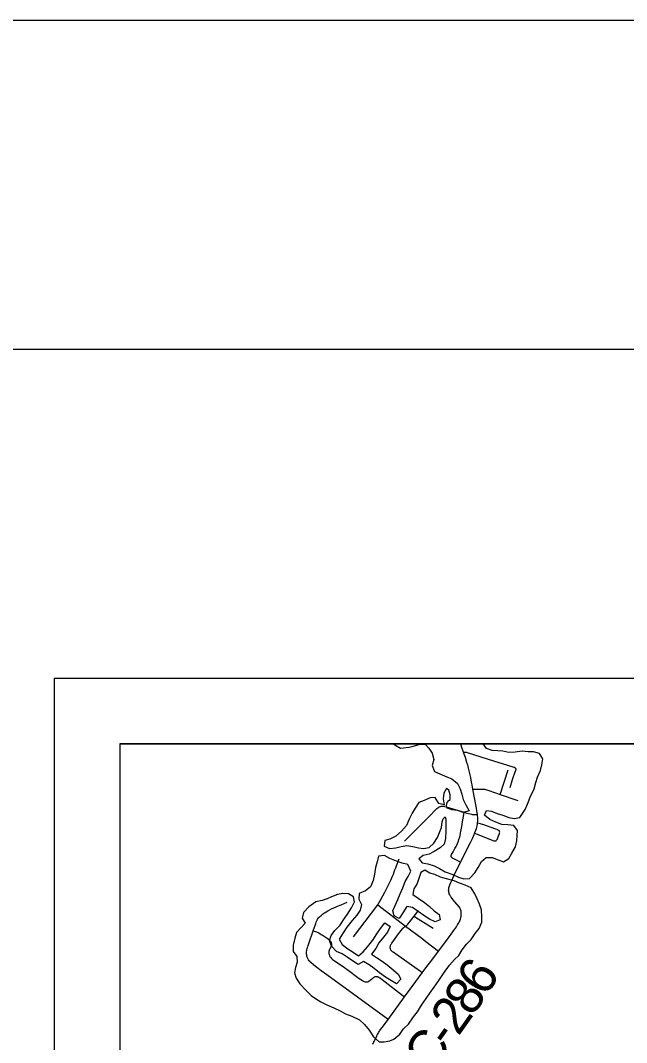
# Model space of a CAD drawing. Extents: x 0 to 34, y -5.4 to 22.
# Drawn here: x 1.949 to 2.87, y 20.446 to 22 of the extents above; entities that cross this region are included whole.
import ezdxf

# ---------------------------------------------------------------- set-up
doc = ezdxf.new("R2010")
doc.units = 0
for name, color, linetype in [('GM_X_County_Road', 7, 'Continuous'), ('GM_X_County_Road_Text', 7, 'Continuous'), ('GM_X_Major_Lake', 7, 'Continuous'), ('GM_X_Rail_Line', 7, 'Continuous'), ('GM_X_Township_Road', 7, 'Continuous'), ('SH_Border', 7, 'Continuous'), ('SH_Cut_Line', 7, 'Continuous'), ('SH_Data', 7, 'Continuous')]:
    doc.layers.add(name, color=color, linetype=linetype)

msp = doc.modelspace()

# ---------------------------------------------------------------- linework, layer by layer
at = {"layer": 'GM_X_County_Road'}
for points in [[(2.5077, 20.4812), (2.533, 20.5158), (2.5499, 20.5391), (2.5596, 20.552), (2.5668, 20.5615), (2.5726, 20.5692), (2.5843, 20.5849), (2.5956, 20.5999), (2.6036, 20.6107), (2.6089, 20.618), (2.6118, 20.6221), (2.6136, 20.625), (2.6151, 20.6276), (2.6162, 20.6295), (2.617, 20.6313), (2.6177, 20.6335), (2.6182, 20.6357), (2.6187, 20.6381), (2.619, 20.6408), (2.6191, 20.6431), (2.619, 20.6448), (2.6188, 20.6457), (2.6185, 20.6472), (2.6181, 20.6484), (2.6172, 20.6504), (2.6157, 20.6526), (2.6092, 20.6602), (2.6066, 20.6633), (2.6052, 20.665), (2.604, 20.6666), (2.6033, 20.6676), (2.6021, 20.6695), (2.6016, 20.6705), (2.6009, 20.672), (2.6006, 20.673), (2.6002, 20.6747), (2.6, 20.6765), (2.5999, 20.6779), (2.6, 20.6795), (2.6002, 20.6812), (2.6006, 20.6831), (2.601, 20.6842), (2.6016, 20.6859), (2.6031, 20.6896), (2.6045, 20.6926), (2.6079, 20.6997), (2.6179, 20.7206), (2.6333, 20.7502), (2.6361, 20.7565), (2.6386, 20.7625), (2.6394, 20.7645), (2.6398, 20.7654), (2.6412, 20.7692), (2.6421, 20.7716), (2.6426, 20.7735), (2.6431, 20.7756), (2.6436, 20.7779), (2.6439, 20.7797), (2.644, 20.7804), (2.6441, 20.7826), (2.6442, 20.7852), (2.6441, 20.7883), (2.6438, 20.7914), (2.6436, 20.7926), (2.6433, 20.7955), (2.6428, 20.7986), (2.6421, 20.8025), (2.6398, 20.8154), (2.6367, 20.8315), (2.6355, 20.8379), (2.6348, 20.842), (2.6342, 20.8453), (2.6335, 20.849), (2.6326, 20.8532), (2.6312, 20.8592), (2.6302, 20.8632), (2.6295, 20.8657), (2.6289, 20.8678), (2.6277, 20.8718), (2.6254, 20.8793), (2.6236, 20.8846), (2.6226, 20.8874), (2.622, 20.8893), (2.6206, 20.8934), (2.6184, 20.8999), (2.6184, 20.9)], [(2.4848, 20.4436), (2.4907, 20.4562), (2.4916, 20.4582), (2.4926, 20.4598), (2.4934, 20.4613), (2.4938, 20.4618), (2.4947, 20.4633), (2.4954, 20.4645), (2.4963, 20.4658), (2.4991, 20.4696), (2.5077, 20.4812)]]:
    msp.add_lwpolyline(points, dxfattribs=at)
at = {"layer": 'GM_X_Major_Lake'}
for points in [[(2.5163, 20.9), (2.518, 20.8988), (2.5267, 20.8938), (2.54, 20.8951), (2.5457, 20.8969), (2.5552, 20.899), (2.5643, 20.8996), (2.5699, 20.8938), (2.575, 20.8861), (2.5775, 20.8762), (2.5747, 20.8672), (2.5783, 20.8584), (2.5866, 20.8544), (2.5969, 20.8503)], [(2.5947, 20.7058), (2.6061, 20.7018), (2.6148, 20.6975), (2.6231, 20.6951), (2.6314, 20.6957), (2.6399, 20.7039), (2.6446, 20.7122), (2.65, 20.7216), (2.6569, 20.7276), (2.666, 20.7274), (2.6754, 20.7239), (2.6834, 20.7211), (2.6914, 20.7259), (2.6961, 20.7342), (2.7015, 20.7439), (2.7035, 20.7526), (2.704, 20.761), (2.7045, 20.7686), (2.699, 20.7759), (2.6899, 20.7771), (2.6808, 20.7777), (2.6714, 20.7812), (2.6627, 20.7852), (2.6545, 20.7917), (2.6573, 20.7989), (2.6652, 20.798), (2.6735, 20.7945), (2.6825, 20.7917), (2.6916, 20.7885), (2.6995, 20.7869), (2.7083, 20.7882), (2.7164, 20.8006), (2.7196, 20.8086), (2.7239, 20.8191), (2.7298, 20.8316), (2.7326, 20.8414), (2.735, 20.8497), (2.7393, 20.8599), (2.7417, 20.8682), (2.743, 20.8773), (2.7382, 20.8857), (2.7287, 20.8881), (2.7208, 20.8883), (2.7117, 20.8892), (2.701, 20.8874), (2.6916, 20.8872), (2.6825, 20.8889), (2.6746, 20.8894), (2.6662, 20.8902), (2.6572, 20.893), (2.6525, 20.9)], [(2.5969, 20.8503), (2.6046, 20.8468), (2.6135, 20.8398), (2.6176, 20.8318), (2.6197, 20.8238), (2.6219, 20.8154), (2.6263, 20.8066), (2.6311, 20.7986), (2.622, 20.7957), (2.6133, 20.7988), (2.6054, 20.8001), (2.5978, 20.8023), (2.5966, 20.8065), (2.5977, 20.8113), (2.6004, 20.8142), (2.6024, 20.8156), (2.6024, 20.8228), (2.6001, 20.8296), (2.5966, 20.8323)], [(2.5966, 20.8323), (2.5925, 20.8255), (2.5916, 20.8168), (2.593, 20.8077), (2.5851, 20.8097), (2.5792, 20.8185), (2.5716, 20.8183), (2.5628, 20.8139), (2.5548, 20.811), (2.5489, 20.8024), (2.5443, 20.7949), (2.5399, 20.7859), (2.5356, 20.7761), (2.5283, 20.7675), (2.5194, 20.7597), (2.5106, 20.7553), (2.503, 20.7531), (2.5017, 20.7448), (2.51, 20.7413), (2.5195, 20.7419), (2.5279, 20.744), (2.5362, 20.7457), (2.5453, 20.7441), (2.554, 20.742), (2.5615, 20.7411), (2.5703, 20.7429), (2.5776, 20.7492), (2.583, 20.7578), (2.5862, 20.7653), (2.589, 20.7729), (2.5899, 20.7816), (2.5915, 20.7861), (2.5946, 20.7895)], [(2.5946, 20.7895), (2.5958, 20.7858), (2.5958, 20.7801), (2.5957, 20.7686), (2.5951, 20.7561), (2.5932, 20.7477), (2.5869, 20.7422), (2.5777, 20.7367), (2.5701, 20.7326), (2.5613, 20.7305), (2.5544, 20.7253), (2.5596, 20.7192), (2.5683, 20.7179), (2.5777, 20.7147), (2.5861, 20.7107), (2.5947, 20.7058)], [(2.5945, 20.6955), (2.5873, 20.6978), (2.579, 20.7014), (2.5711, 20.7038), (2.5636, 20.7081), (2.5575, 20.7044), (2.5519, 20.6878), (2.5472, 20.6796), (2.5455, 20.6713), (2.5534, 20.6654), (2.5631, 20.6592), (2.5706, 20.653), (2.5781, 20.6464), (2.5855, 20.641), (2.5869, 20.6326), (2.5793, 20.6297), (2.5706, 20.6337), (2.5624, 20.6391), (2.5534, 20.6453), (2.5448, 20.6512), (2.5361, 20.6532), (2.5303, 20.6435), (2.5248, 20.6345), (2.5169, 20.6388), (2.5148, 20.6464), (2.5187, 20.6547), (2.5227, 20.6637), (2.5262, 20.6724), (2.5302, 20.6814), (2.5337, 20.6908), (2.5384, 20.6987), (2.5424, 20.7066), (2.5376, 20.7169), (2.5293, 20.7186), (2.5206, 20.7217), (2.5105, 20.7261), (2.5022, 20.7304), (2.4931, 20.7294), (2.4911, 20.7211), (2.4887, 20.7121), (2.4873, 20.7019), (2.4853, 20.6924), (2.481, 20.683), (2.4736, 20.6767), (2.4641, 20.6727), (2.4632, 20.664), (2.4676, 20.6559)], [(2.5923, 20.551), (2.6014, 20.5637), (2.6087, 20.5723), (2.6156, 20.5787), (2.6203, 20.5873), (2.6269, 20.5959), (2.6342, 20.6027), (2.6404, 20.6117), (2.6462, 20.6196), (2.6505, 20.629), (2.6506, 20.6373), (2.6496, 20.648), (2.6468, 20.6567), (2.6435, 20.6644), (2.6398, 20.6724), (2.6339, 20.6812), (2.6248, 20.6856), (2.6162, 20.6883), (2.6083, 20.6919), (2.5945, 20.6955)], [(2.4676, 20.6559), (2.4652, 20.6476), (2.4601, 20.6398), (2.4532, 20.6316), (2.445, 20.6215), (2.4396, 20.6128), (2.4334, 20.6031), (2.4378, 20.595), (2.4464, 20.5884), (2.4546, 20.5834), (2.4628, 20.5779), (2.4698, 20.5839), (2.4767, 20.5917), (2.4848, 20.6018), (2.4907, 20.6112), (2.4965, 20.6194), (2.5031, 20.628), (2.511, 20.6226), (2.5067, 20.6139), (2.5008, 20.6061), (2.4939, 20.5975), (2.4892, 20.5892), (2.4826, 20.5806), (2.4904, 20.5752), (2.4987, 20.5697), (2.5065, 20.5643), (2.5155, 20.5569), (2.5233, 20.55), (2.5274, 20.5427), (2.5208, 20.5356), (2.5129, 20.5399), (2.5039, 20.5454), (2.4946, 20.552), (2.4867, 20.5586), (2.4793, 20.5644), (2.4703, 20.5691), (2.4622, 20.5647), (2.4536, 20.5705), (2.4454, 20.576), (2.4379, 20.581), (2.4292, 20.5846), (2.4218, 20.5927), (2.4189, 20.6014), (2.4213, 20.609), (2.4271, 20.6165), (2.4349, 20.6247), (2.4399, 20.6329), (2.4461, 20.6415), (2.4524, 20.6509), (2.4567, 20.6599), (2.4553, 20.6675), (2.4474, 20.6722), (2.4391, 20.6727), (2.4311, 20.6714), (2.4216, 20.6674), (2.4151, 20.6644), (2.4075, 20.6619), (2.398, 20.6602), (2.3872, 20.6524), (2.3791, 20.6438), (2.3771, 20.6351), (2.3815, 20.6275), (2.3757, 20.6211), (2.3684, 20.6133), (2.366, 20.605), (2.3635, 20.5944), (2.3633, 20.5846), (2.3689, 20.5769), (2.3695, 20.5682), (2.3671, 20.5603), (2.3654, 20.5519), (2.3679, 20.5439), (2.3735, 20.5355), (2.3835, 20.5255), (2.391, 20.5178), (2.3973, 20.5131), (2.4056, 20.508), (2.4149, 20.5033), (2.4251, 20.499), (2.4349, 20.4942), (2.4431, 20.4899), (2.4529, 20.4863), (2.4642, 20.4808), (2.472, 20.4735), (2.479, 20.4647), (2.4857, 20.4547), (2.4943, 20.447), (2.5019, 20.4472), (2.5106, 20.4486), (2.5167, 20.4511), (2.5255, 20.4589), (2.531, 20.4672), (2.5387, 20.4742), (2.5465, 20.4851), (2.5523, 20.4926), (2.5585, 20.5031), (2.5659, 20.5132), (2.5713, 20.5214), (2.5779, 20.5304), (2.5849, 20.5405), (2.5923, 20.551)]]:
    msp.add_lwpolyline(points, dxfattribs=at)
at = {"layer": 'GM_X_Rail_Line'}
msp.add_lwpolyline([(3.5133, 20.9), (2.1, 20.9), (2.1, 20.2033), (2.1537, 20.2026), (3.2417, 20.1756), (3.4778, 20.1697), (3.5122, 20.8763)], close=True, dxfattribs=at)
at = {"layer": 'GM_X_Township_Road'}
for p, q in [((2.6784, 20.8232), (2.6903, 20.8606)), ((2.4551, 20.6066), (2.4922, 20.6555))]:
    msp.add_line(p, q, dxfattribs=at)
for points in [[(2.6226, 20.8874), (2.6233, 20.8875), (2.6243, 20.8876), (2.6257, 20.8876), (2.6268, 20.8874), (2.6283, 20.887), (2.6697, 20.8737), (2.6811, 20.8703), (2.6977, 20.8655), (2.6989, 20.865), (2.6998, 20.8647), (2.7004, 20.8643), (2.7007, 20.864), (2.7011, 20.8636), (2.7014, 20.8633), (2.7016, 20.8629), (2.7018, 20.8622), (2.7018, 20.8619), (2.7018, 20.8614), (2.7018, 20.8611), (2.7018, 20.8608), (2.7017, 20.8605), (2.7017, 20.8603), (2.7016, 20.8599), (2.7014, 20.8593), (2.7012, 20.8586), (2.6967, 20.8454), (2.6927, 20.8336)], [(2.6367, 20.8315), (2.651, 20.8315), (2.653, 20.8314), (2.6542, 20.8313), (2.6551, 20.8311), (2.6558, 20.8309), (2.6573, 20.8304), (2.6581, 20.8301), (2.6608, 20.8292), (2.6784, 20.8232), (2.705, 20.8142)], [(2.5328, 20.7521), (2.5731, 20.793), (2.5779, 20.7979), (2.5821, 20.8019), (2.5836, 20.8031), (2.5845, 20.8037), (2.5854, 20.8043), (2.586, 20.8046), (2.5868, 20.8049), (2.5877, 20.8052), (2.5885, 20.8054), (2.5891, 20.8055), (2.5897, 20.8055), (2.5908, 20.8056), (2.5917, 20.8055), (2.593, 20.8053), (2.5938, 20.8052), (2.5959, 20.8046), (2.6235, 20.7963), (2.6276, 20.795), (2.6327, 20.7936), (2.6344, 20.7931), (2.6356, 20.7929), (2.6365, 20.7928), (2.6374, 20.7927), (2.6379, 20.7926), (2.6392, 20.7926), (2.6399, 20.7926), (2.6436, 20.7926)], [(2.6179, 20.7206), (2.6078, 20.7255), (2.6059, 20.7264), (2.6056, 20.7266), (2.6051, 20.727), (2.6047, 20.7273), (2.6044, 20.7276), (2.6041, 20.7281), (2.6038, 20.7287), (2.6037, 20.7291), (2.6036, 20.7296), (2.6036, 20.73), (2.6037, 20.7305), (2.6038, 20.731), (2.604, 20.7314), (2.6043, 20.732), (2.6051, 20.7333), (2.6067, 20.7359), (2.6095, 20.741), (2.6111, 20.744), (2.6124, 20.7464), (2.6135, 20.7489), (2.6144, 20.7513), (2.616, 20.7561), (2.6167, 20.7586), (2.6172, 20.761), (2.618, 20.7647), (2.619, 20.7696), (2.6199, 20.7747), (2.6212, 20.7819), (2.623, 20.7928), (2.6235, 20.7963)], [(2.6394, 20.7645), (2.6686, 20.7529), (2.6704, 20.7526), (2.6717, 20.7528), (2.6722, 20.753), (2.6729, 20.7536), (2.6734, 20.7542), (2.6738, 20.755), (2.6762, 20.7613), (2.6772, 20.764), (2.6774, 20.765), (2.6775, 20.7661), (2.6773, 20.767), (2.677, 20.7677), (2.6766, 20.7683), (2.6761, 20.7687), (2.6754, 20.7692), (2.6744, 20.7697), (2.6735, 20.77), (2.6718, 20.7707), (2.6518, 20.7775), (2.6508, 20.7778), (2.6485, 20.7785), (2.6464, 20.7791), (2.6439, 20.7797)], [(2.503, 20.6749), (2.5081, 20.685), (2.5103, 20.6897), (2.5118, 20.6931), (2.5145, 20.6991), (2.5159, 20.7023), (2.5173, 20.7059), (2.5183, 20.7085), (2.5195, 20.7118), (2.5206, 20.7147), (2.5216, 20.7174), (2.5246, 20.7254)], [(2.4922, 20.6555), (2.4948, 20.6598), (2.497, 20.6636), (2.503, 20.6749)], [(2.3841, 20.5791), (2.3839, 20.5806), (2.3839, 20.5812), (2.3839, 20.5818), (2.3839, 20.583), (2.384, 20.5839), (2.3843, 20.586), (2.3845, 20.5871), (2.3849, 20.5889), (2.3853, 20.5904), (2.3857, 20.5916), (2.3864, 20.5936), (2.3873, 20.5967), (2.394, 20.6162), (2.3958, 20.6213), (2.3974, 20.6258), (2.3978, 20.627), (2.3986, 20.629), (2.399, 20.6301), (2.3997, 20.6315), (2.4, 20.6323), (2.4007, 20.6335), (2.4011, 20.6343), (2.402, 20.6355), (2.4037, 20.6374), (2.4059, 20.6395), (2.4078, 20.6409), (2.4103, 20.6427), (2.4119, 20.6437), (2.4163, 20.6463), (2.4216, 20.6492), (2.4254, 20.651), (2.4287, 20.6525), (2.431, 20.6535), (2.4363, 20.6556), (2.4458, 20.6593)], [(2.4922, 20.6555), (2.5344, 20.6229), (2.559, 20.6046), (2.5652, 20.5999), (2.5843, 20.5849)], [(2.5344, 20.6229), (2.5354, 20.6236), (2.5362, 20.6242), (2.537, 20.625), (2.538, 20.6261), (2.5402, 20.629), (2.5473, 20.6381), (2.554, 20.6468)], [(2.5473, 20.6381), (2.5493, 20.6368), (2.5763, 20.6198)], [(2.5596, 20.552), (2.5569, 20.5539), (2.5155, 20.5835), (2.5146, 20.5842), (2.5139, 20.5847), (2.5135, 20.5851), (2.513, 20.5856), (2.5126, 20.586), (2.5121, 20.5868), (2.5118, 20.5873), (2.5116, 20.5879), (2.5114, 20.5888), (2.5112, 20.59), (2.5112, 20.591), (2.5112, 20.5918), (2.5113, 20.5927), (2.5115, 20.5934), (2.5117, 20.5942), (2.5122, 20.5953), (2.5128, 20.5961), (2.5136, 20.5974), (2.5238, 20.6112), (2.5297, 20.6192), (2.53, 20.6195), (2.5303, 20.6199), (2.5304, 20.6201), (2.5307, 20.6204), (2.531, 20.6206), (2.5313, 20.6209), (2.5316, 20.6211), (2.5321, 20.6214), (2.5333, 20.6222), (2.5344, 20.6229)], [(2.394, 20.6162), (2.3988, 20.6143), (2.4024, 20.6127), (2.4046, 20.6116), (2.4073, 20.61), (2.4091, 20.6089), (2.4121, 20.607), (2.4151, 20.605), (2.417, 20.6034), (2.4181, 20.6025), (2.4194, 20.6011), (2.4202, 20.6002), (2.4206, 20.5996), (2.4211, 20.5987), (2.4214, 20.5977), (2.4217, 20.5964), (2.4219, 20.595), (2.4218, 20.5943), (2.4217, 20.5936), (2.4216, 20.5931), (2.4215, 20.5927), (2.4212, 20.5921), (2.4209, 20.5914), (2.4191, 20.5883), (2.4187, 20.5874), (2.4184, 20.5867), (2.4181, 20.5858), (2.4179, 20.5848), (2.4178, 20.5841), (2.4178, 20.5827), (2.4179, 20.5815), (2.4182, 20.5798), (2.4185, 20.5789), (2.4189, 20.5778), (2.4193, 20.577), (2.4206, 20.5753), (2.4218, 20.574), (2.4234, 20.5726), (2.4303, 20.5679), (2.4416, 20.56), (2.447, 20.5562), (2.4619, 20.5451), (2.4641, 20.5436), (2.4664, 20.542), (2.4687, 20.5404), (2.4706, 20.5393), (2.4717, 20.5388), (2.4729, 20.5384), (2.4737, 20.5383), (2.4747, 20.5382), (2.4754, 20.5382), (2.4765, 20.5384), (2.477, 20.5385), (2.4779, 20.5388), (2.4784, 20.5391), (2.4793, 20.5398), (2.4803, 20.5406), (2.4831, 20.543), (2.4846, 20.5442), (2.4856, 20.545), (2.4865, 20.5456), (2.4874, 20.546), (2.4884, 20.5463), (2.4891, 20.5465), (2.49, 20.5465), (2.4907, 20.5465), (2.4915, 20.5464), (2.492, 20.5462), (2.4929, 20.5459), (2.4938, 20.5455), (2.4954, 20.5445), (2.4963, 20.5438), (2.4987, 20.542), (2.533, 20.5158)], [(2.5077, 20.4812), (2.4148, 20.5491), (2.4062, 20.5552), (2.3993, 20.5603), (2.3975, 20.5617), (2.3944, 20.5644), (2.3905, 20.568), (2.3887, 20.5697), (2.3879, 20.5705), (2.3868, 20.572), (2.3861, 20.573), (2.3857, 20.5738), (2.3851, 20.575), (2.3848, 20.5758), (2.3843, 20.5775), (2.3841, 20.5791)]]:
    msp.add_lwpolyline(points, dxfattribs=at)
at = {"layer": 'SH_Border'}
msp.add_lwpolyline([(1.5, 21.5), (33.5, 21.5), (33.5, 0.5), (1.5, 0.5)], close=True, dxfattribs=at)
at = {"layer": 'SH_Cut_Line'}
msp.add_lwpolyline([(0, 0), (34, 0), (34, 22), (0, 22)], close=True, dxfattribs=at)
at = {"layer": 'SH_Data'}
for p, q in [((2, 21), (9, 21)), ((2, 21), (2, 14)), ((2.1, 20.9), (2.1, 14.1)), ((2.1, 20.9), (8.9, 20.9))]:
    msp.add_line(p, q, dxfattribs=at)

# ---------------------------------------------------------------- texts
at = {"layer": 'GM_X_County_Road_Text'}
for s, rotation, p in [('6', 57.1647, (2.6563, 20.5145)), ('8', 55.578, (2.6356, 20.4842)), ('2', 54.5802, (2.6147, 20.4548)), ('C', 56.0523, (2.5753, 20.3974)), ('-', 54.5712, (2.6011, 20.4358))]:
    msp.add_text(s, height=0.0568, rotation=rotation, dxfattribs=at).set_placement(p)

doc.saveas('drawing.dxf')
